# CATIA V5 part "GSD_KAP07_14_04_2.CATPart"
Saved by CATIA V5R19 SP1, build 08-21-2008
Part number: GSD_KAP07_14_04
Definition: Beispielmodell für die Funktion Formverrundung / Shape Fillet.
Description: CATIA V5 Flächenmodellierung  Copyright (c) 2009 Maik Hertha IT Consultants
Bounding box of the stored display mesh (mm): x -24.222 to 45, y -22.632 to 60, z 10 to 45
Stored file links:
  \GSD_BUCH_UEBUNG\GSD_KAP07_14_04_2.CATPart
  \XV5_ABNAHME_1.0\XV5_BLEND_FILLET_01.CATPart
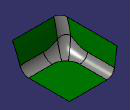
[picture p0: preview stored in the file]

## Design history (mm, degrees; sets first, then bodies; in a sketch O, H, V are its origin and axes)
AxisSystem1 "Absolute Axis System": origin (0, 0, 0), X (1, 0, 0), Y (0, 1, 0), Z (0, 0, 1)
Set1 "Basis_Flaechen"
  Plane1: type Equation, A 0, B 0, C 1, Length 10
  Point1: type OnPlane, Support Plane1, Direction (1, 0, 0), H 10, V -10
  Plane2: type Equation, A 1, B 0, C 0, Length 10
  Plane3: type Equation, A 0, B 1, C 0, Length 0
  Sketch1 on Plane1, origin (10, -10, 10), H (0, 1, 0), V (-1, 0, 0)
    line L1 (0, 35) -> (70, 35)
    line L2 (70, 35) -> (70, -35)
    line L3 (70, -35) -> (0, -35)
    line L4 (0, -35) -> (0, 35)
    curve C1
    construction line L5 (93.4795, 0) -> (-28.9576, 0)
    point P5 (93.4795, 0)
    length L3 = 70
    length L2 = 70 {= Sketch1.length(L3)}
    horizontal: L1 H, L3 H, L5 H
    vertical: L2 V, L4 V
    coincidence: P5 H
    symmetry: L1 L3 L5
  Sketch2 on Plane2, origin (10, -10, 10), H (0, 1, 0), V (0, 0, 1)
    spline S1 through (-12.6316, 35) (-0.0027, 3.7447) (5.7378, -31.331)
    curve C1
    construction line L1 (-28.3244, 0) -> (83.7309, 0)
    point P1 (-28.3244, 0)
    point P3 (-12.6316, 35)
    distance L1 P3 = 35
    coincidence: P1 H
    horizontal: L1 H
  Split1: ToCut Plane1, Cutting Sketch1.C1
  Extrude1: Lim1 35, Lim2 35, Element1 Sketch2.C1, Direction Plane2
  Sketch3 on Plane3, origin (10, 0, 10), H (-1, 0, 0), V (0, 0, 1)
    spline S1 through (26.9876, -31.1238) (28.765, -3.6881) (34.2216, 35)
    curve C1
    point P1 (34.2216, 35)
    distance P1 H = 35
  Extrude2: Lim1 60, Lim2 23, Element1 Sketch3.C1, Direction Plane3
Set2 "Formverrundung"
  DatumSurface1 to DatumSurface3: linked copy from another document
  Intersect1: ToIntersect1 DatumSurface2, ToIntersect2 DatumSurface1
  Intersect2: ToIntersect1 DatumSurface1, ToIntersect2 DatumSurface3
  CurvePar1: Support DatumSurface1, Offset1 10, Offset2 15, Offset Intersect1
  CurvePar2: Support DatumSurface1, Offset1 10, Offset2 15, Offset Intersect2
  Intersect3: ToIntersect1 CurvePar1, ToIntersect2 CurvePar2
  Point2: type OnCurve, Support CurvePar1, Length 20, RefPoint Intersect3
  Point3: type OnCurve, Support CurvePar2, Length 20, RefPoint Intersect3
  Connect1: Curve1 CurvePar1, Curve2 CurvePar2, Tension1 1.2, Tension2 1.2, Point1 Point2, Point2 Point3
  Fillet1: type BiTangent, Element1 DatumSurface2, Element2 DatumSurface3, Radius 10
  Fillet2: type BiTangent, Spine Connect1, Element1 DatumSurface1, Element2 Fillet1, Radius 10
Body1 (main body)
